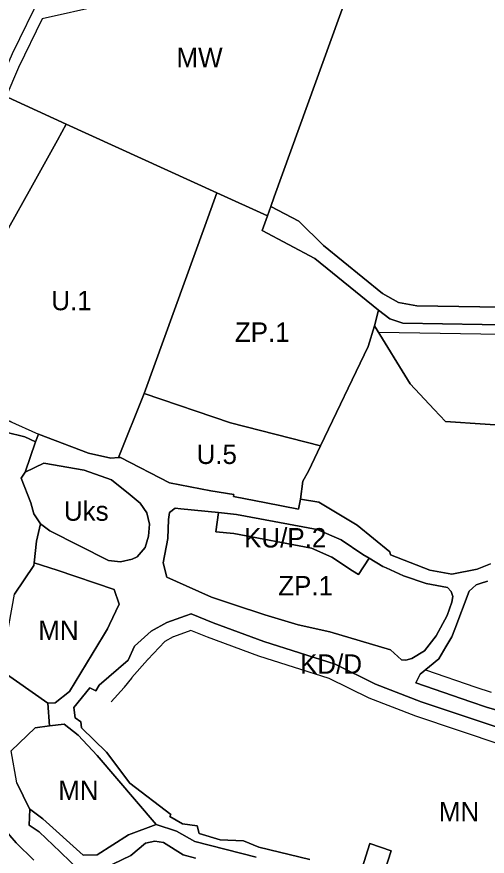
# Model space of a CAD drawing. Extents: x 7438199 to 7440548, y 5549253 to 5551017.
# Drawn here: x 7438917.7 to 7439160, y 5550359.8 to 5550792.4 of the extents above; entities that cross this region are included whole.
import ezdxf

# ---------------------------------------------------------------- set-up
doc = ezdxf.new("R2010")
doc.units = 0
for name, color, linetype in [('linie_rozgraniczajace', 7, 'Continuous'), ('linie_zabudowy_nieprzekraczalne', 7, 'Continuous'), ('oznaczenia_przeznaczen', 7, 'Continuous')]:
    doc.layers.add(name, color=color, linetype=linetype)

msp = doc.modelspace()

# ---------------------------------------------------------------- linework, layer by layer
at = {"layer": 'linie_rozgraniczajace'}
for points in [[(7439177.79, 5550642.53), (7439123.74, 5550643.4), (7439114.3, 5550645.13), (7439106.06, 5550649.82), (7439075.72, 5550674.59), (7439062.98, 5550687.02), (7439048.59, 5550694.66), (7439050.34, 5550699.54), (7439092.49, 5550816.41), (7439102.58, 5550833.38), (7439108.69, 5550843.65), (7439167.88, 5550856.79)], [(7439179.38, 5550581.08), (7439138.49, 5550583.87), (7439132.67, 5550590.05), (7439120.33, 5550603.16), (7439101.88, 5550633.22), (7439104.03, 5550641.16), (7439109.78, 5550636.73), (7439116.56, 5550634.52), (7439177.91, 5550633.53)], [(7439161.71, 5550510.48), (7439154.78, 5550507.8), (7439141.85, 5550505.11), (7439130.53, 5550507.27), (7439110.16, 5550515.09), (7439109.86, 5550516.66), (7439093.02, 5550530.41), (7439073.3, 5550542.24), (7439063.8, 5550543.89), (7439065.05, 5550553.1), (7439067.91, 5550558.25), (7439074.21, 5550571.36), (7439098.71, 5550622.41), (7439101.88, 5550633.22), (7439120.33, 5550603.16), (7439132.67, 5550590.05), (7439138.49, 5550583.87), (7439179.38, 5550581.08)], [(7438912.06, 5550578.32), (7438921.86, 5550575.86), (7438927.29, 5550573.44), (7438921.93, 5550557.8), (7438919.98, 5550554.57), (7438925, 5550541.97), (7438926.54, 5550536.25), (7438929.88, 5550531.11), (7438927.79, 5550522.1), (7438926.58, 5550511), (7438926.49, 5550509.6), (7438916.57, 5550494.9)], [(7438921.93, 5550557.8), (7438927.29, 5550573.44), (7438928.95, 5550577.22), (7438954.64, 5550567.5), (7438966.11, 5550565.02), (7438970.07, 5550565.25), (7438971.03, 5550565.31), (7438996.38, 5550552.24), (7439017.67, 5550548.08), (7439029.5, 5550546.2), (7439029.24, 5550545.14), (7439046.12, 5550541.89), (7439062.82, 5550538.64), (7439063.8, 5550543.89), (7439073.3, 5550542.24), (7439093.02, 5550530.41), (7439109.86, 5550516.66), (7439110.16, 5550515.09), (7439130.53, 5550507.27), (7439141.85, 5550505.11), (7439154.78, 5550507.8), (7439161.71, 5550510.48)], [(7439040.93, 5550359.25), (7439009.39, 5550367.36), (7439000.02, 5550372.78), (7438989.51, 5550376.09), (7438959.12, 5550411.62), (7438949.38, 5550422.2), (7438942.08, 5550427.87), (7438934.63, 5550426.93), (7438933.68, 5550438.7), (7438937.38, 5550438.78), (7438944.88, 5550444.76), (7438962.44, 5550473.61), (7438964.49, 5550476.99), (7438965.51, 5550479.19), (7438970.36, 5550489.69), (7438967.77, 5550497.26), (7438938.54, 5550507.28), (7438926.58, 5550511), (7438927.79, 5550522.1), (7438929.88, 5550531.11), (7438934.7, 5550527.53), (7438964.92, 5550512.24), (7438971.16, 5550511.59), (7438977.1, 5550512.88), (7438979.77, 5550514.16), (7438983.79, 5550518.87), (7438985.55, 5550524.69), (7438986.13, 5550530.93), (7438984.7, 5550536.84), (7438981.17, 5550541.81), (7438976.18, 5550546.03), (7438966.53, 5550553.83), (7438952.32, 5550558.75), (7438931.59, 5550562.33), (7438921.93, 5550557.8)], [(7438926.4, 5550357.75), (7438917.29, 5550366.61), (7438914.15, 5550370.51), (7438911.03, 5550374.37), (7438905.07, 5550382.61), (7438904.82, 5550391.79), (7438904.81, 5550391.93), (7438900.69, 5550408.48), (7438896.57, 5550425.02), (7438896.35, 5550434.12), (7438895.93, 5550434.08), (7438895.8, 5550440.56), (7438895.66, 5550447.04), (7438898.89, 5550478.66), (7438902.26, 5550498.06), (7438904.14, 5550511.19), (7438906.44, 5550525.8), (7438906.48, 5550528.4), (7438906.82, 5550532.42), (7438905.55, 5550538.97), (7438898.26, 5550554.64), (7438894.22, 5550560.43)], [(7439165.04, 5550435.05), (7439159.63, 5550436.68), (7439151.52, 5550439.4), (7439123.16, 5550449.19), (7439125.46, 5550453.6), (7439135.13, 5550461.44), (7439138.77, 5550467.69), (7439141.82, 5550472.91), (7439143.26, 5550476.75), (7439150.65, 5550496.42), (7439152.47, 5550498.02), (7439154.28, 5550499.62), (7439156.39, 5550500.39), (7439160.1, 5550501.6)], [(7439160.1, 5550501.6), (7439156.39, 5550500.39), (7439154.28, 5550499.62), (7439152.47, 5550498.02), (7439150.65, 5550496.42), (7439143.26, 5550476.75), (7439141.82, 5550472.91), (7439138.77, 5550467.69), (7439135.13, 5550461.44), (7439125.46, 5550453.6), (7439123.16, 5550449.19), (7439151.52, 5550439.4), (7439159.63, 5550436.68), (7439165.04, 5550435.05)], [(7439068.64, 5550358.03), (7439042.41, 5550364.47), (7439034.53, 5550367.69), (7439022.39, 5550368.18), (7439011.58, 5550371.45), (7439010.52, 5550375.5), (7439003.12, 5550376.46), (7438996.56, 5550380.24), (7438997.01, 5550381.31), (7438975.91, 5550397.51), (7438963.83, 5550413.48), (7438951.11, 5550426), (7438950.63, 5550428.97), (7438947.82, 5550431.05), (7438947.14, 5550436.52), (7438955.32, 5550446.51), (7438958.4, 5550445), (7438960.11, 5550447.98), (7438975.12, 5550460.85), (7438978.33, 5550468.09), (7438986.91, 5550475.78), (7438994.99, 5550480.18), (7439004.67, 5550483.68), (7439007.52, 5550484.71), (7439018.81, 5550480.12), (7439044.91, 5550470.46), (7439081.63, 5550458.83), (7439102.44, 5550448.53), (7439125.97, 5550439.44), (7439170.32, 5550424.55)], [(7439170.32, 5550424.55), (7439125.97, 5550439.44), (7439102.44, 5550448.53), (7439081.63, 5550458.83), (7439044.91, 5550470.46), (7439018.81, 5550480.12), (7439007.52, 5550484.71), (7439004.67, 5550483.68), (7438994.99, 5550480.18), (7438986.91, 5550475.78), (7438978.33, 5550468.09), (7438975.12, 5550460.85), (7438960.11, 5550447.98), (7438958.4, 5550445), (7438955.32, 5550446.51), (7438947.14, 5550436.52), (7438947.82, 5550431.05), (7438950.63, 5550428.97), (7438951.11, 5550426), (7438963.83, 5550413.48), (7438975.91, 5550397.51), (7438997.01, 5550381.31), (7438996.56, 5550380.24), (7439003.12, 5550376.46), (7439010.52, 5550375.5), (7439011.58, 5550371.45), (7439022.39, 5550368.18), (7439034.53, 5550367.69), (7439042.41, 5550364.47), (7439068.64, 5550358.03)], [(7438909.55, 5550455.66), (7438933.68, 5550438.7), (7438934.63, 5550426.93), (7438927.18, 5550426), (7438914.85, 5550414.19)], [(7438787.79, 5550355.53), (7438796.75, 5550368.59), (7438813.34, 5550396.85), (7438817.34, 5550400.58), (7438821.33, 5550404.09), (7438826.88, 5550406.22), (7438833.47, 5550406.62), (7438840.95, 5550404.64), (7438845.84, 5550402.45), (7438864.2, 5550394.06), (7438882.86, 5550385.45), (7438886.22, 5550391.53), (7438905.07, 5550382.61), (7438911.03, 5550374.37), (7438914.15, 5550370.51), (7438917.29, 5550366.61), (7438926.4, 5550357.75)], [(7438917.65, 5550397.54), (7438924.31, 5550384.19), (7438924.35, 5550384.13), (7438924.1, 5550375.84), (7438929.23, 5550372.42), (7438939.98, 5550362.05), (7438950.72, 5550351.67)], [(7438950.72, 5550351.67), (7438939.98, 5550362.05), (7438929.23, 5550372.42), (7438924.1, 5550375.84), (7438924.35, 5550384.13), (7438924.31, 5550384.19), (7438931.15, 5550379.14), (7438951.8, 5550360.38), (7438959.14, 5550360.57), (7438975.32, 5550370.81), (7438989.51, 5550376.09), (7439000.02, 5550372.78), (7439009.39, 5550367.36), (7439040.93, 5550359.25)], [(7438958.22, 5550351.34), (7438976.46, 5550360.11), (7438983.99, 5550366.45), (7438988.75, 5550367.61), (7438993.22, 5550366.92), (7439003.36, 5550360.49), (7439009.74, 5550358.8)], [(7439009.74, 5550358.8), (7439003.36, 5550360.49), (7438993.22, 5550366.92), (7438988.75, 5550367.61), (7438983.99, 5550366.45), (7438976.46, 5550360.11), (7438958.22, 5550351.34)], [(7439106.84, 5550351.42), (7439110.46, 5550362.5), (7439105.01, 5550364.44), (7439099.56, 5550366.37), (7439095.55, 5550353.74)], [(7439095.55, 5550353.74), (7439099.56, 5550366.37), (7439105.01, 5550364.44), (7439110.46, 5550362.5), (7439106.84, 5550351.42)]]:
    msp.add_lwpolyline(points, dxfattribs=at)
for points in [[(7438906.66, 5550753.65), (7438915.42, 5550773.41), (7438930.38, 5550804.29), (7438991.1, 5550818.07), (7439026, 5550825.99), (7439042.73, 5550830.95), (7439048.59, 5550832.62), (7439095.81, 5550842.97), (7439096.81, 5550837.3), (7439096, 5550833.11), (7439095.84, 5550832.32), (7439096.59, 5550828.7), (7439092.49, 5550816.41), (7439050.34, 5550699.54), (7439048.59, 5550694.66), (7439046.85, 5550689.8), (7439020.82, 5550701.66), (7438943.17, 5550737.02)], [(7438864.25, 5550654.48), (7438868.71, 5550671.05), (7438876.14, 5550698.63), (7438889.91, 5550723.46), (7438903.68, 5550748.28), (7438906.66, 5550753.65), (7438943.17, 5550737.02), (7438938.66, 5550728.88), (7438924.89, 5550704.05), (7438913.49, 5550683.5), (7438907.33, 5550660.65), (7438902.8, 5550643.82)], [(7438856.2, 5550623.73), (7438861.28, 5550643.47), (7438864.25, 5550654.48), (7438902.8, 5550643.82), (7438907.33, 5550660.65), (7438913.49, 5550683.5), (7438924.89, 5550704.05), (7438938.66, 5550728.88), (7438943.17, 5550737.02), (7439020.82, 5550701.66), (7439014.6, 5550684.53), (7438983.31, 5550598.22), (7438970.07, 5550565.25), (7438966.11, 5550565.02), (7438954.64, 5550567.5), (7438928.95, 5550577.22), (7438927.29, 5550573.44), (7438921.86, 5550575.86), (7438912.06, 5550578.32), (7438889.4, 5550590.35), (7438870.1, 5550605.3)], [(7438983.31, 5550598.22), (7439014.6, 5550684.53), (7439020.82, 5550701.66), (7439046.85, 5550689.8), (7439044.17, 5550682.29), (7439071.27, 5550667.9), (7439104.03, 5550641.16), (7439101.88, 5550633.22), (7439098.71, 5550622.41), (7439074.21, 5550571.36), (7439027.76, 5550583.08)], [(7439044.17, 5550682.29), (7439046.85, 5550689.8), (7439048.59, 5550694.66), (7439062.98, 5550687.02), (7439075.72, 5550674.59), (7439106.06, 5550649.82), (7439114.3, 5550645.13), (7439123.74, 5550643.4), (7439177.79, 5550642.53), (7439322.46, 5550644.44), (7439329.12, 5550654), (7439340.07, 5550623.13), (7439312.46, 5550633.66), (7439302.38, 5550636.01), (7439253.6, 5550634.86), (7439239.07, 5550634.34), (7439177.91, 5550633.53), (7439116.56, 5550634.52), (7439109.78, 5550636.73), (7439104.03, 5550641.16), (7439071.27, 5550667.9)], [(7438970.07, 5550565.25), (7438983.31, 5550598.22), (7439027.76, 5550583.08), (7439074.21, 5550571.36), (7439067.91, 5550558.25), (7439065.05, 5550553.1), (7439063.8, 5550543.89), (7439062.82, 5550538.64), (7439046.12, 5550541.89), (7439029.24, 5550545.14), (7439029.5, 5550546.2), (7439017.67, 5550548.08), (7438996.38, 5550552.24), (7438971.03, 5550565.31)], [(7438919.98, 5550554.57), (7438921.93, 5550557.8), (7438931.59, 5550562.33), (7438952.32, 5550558.75), (7438966.53, 5550553.83), (7438976.18, 5550546.03), (7438981.17, 5550541.81), (7438984.7, 5550536.84), (7438986.13, 5550530.93), (7438985.55, 5550524.69), (7438983.79, 5550518.87), (7438979.77, 5550514.16), (7438977.1, 5550512.88), (7438971.16, 5550511.59), (7438964.92, 5550512.24), (7438934.7, 5550527.53), (7438929.88, 5550531.11), (7438926.54, 5550536.25), (7438925, 5550541.97)], [(7438993.01, 5550511), (7438995.51, 5550523.51), (7438995.9, 5550533.35), (7438996.44, 5550537.02), (7438999.28, 5550539.11), (7439002.15, 5550538.82), (7439021.65, 5550536.86), (7439020.29, 5550526.95), (7439029.47, 5550526.03), (7439069.48, 5550518.61), (7439079.93, 5550513.99), (7439090.61, 5550506.88), (7439093.79, 5550504.94), (7439099.26, 5550513.32), (7439106.17, 5550509.1), (7439107.89, 5550508.34), (7439116.96, 5550504.33), (7439128.52, 5550500.43), (7439139.47, 5550498.21), (7439141.39, 5550496.22), (7439142.34, 5550493.63), (7439141.78, 5550490.65), (7439139.32, 5550483.93), (7439133.79, 5550473.43), (7439127.71, 5550465.71), (7439121.16, 5550461.66), (7439118, 5550460.85), (7439115.78, 5550460.94), (7439110.11, 5550466.11), (7439078.96, 5550475.41), (7439062.7, 5550479.1), (7439045.53, 5550484.16), (7439029.25, 5550489.56), (7439018.04, 5550493.29), (7439004.93, 5550499.13), (7438994.96, 5550503.56)], [(7438993.01, 5550511), (7438994.96, 5550503.56), (7439004.93, 5550499.13), (7439018.04, 5550493.29), (7439029.25, 5550489.56), (7439045.53, 5550484.16), (7439062.7, 5550479.1), (7439078.96, 5550475.41), (7439110.11, 5550466.11), (7439115.78, 5550460.94), (7439118, 5550460.85), (7439121.16, 5550461.66), (7439127.71, 5550465.71), (7439133.79, 5550473.43), (7439139.32, 5550483.93), (7439141.78, 5550490.65), (7439142.34, 5550493.63), (7439141.39, 5550496.22), (7439139.47, 5550498.21), (7439128.52, 5550500.43), (7439116.96, 5550504.33), (7439107.89, 5550508.34), (7439106.17, 5550509.1), (7439099.26, 5550513.32), (7439095.99, 5550515.31), (7439084.76, 5550522.79), (7439072.45, 5550528.22), (7439030.89, 5550535.93), (7439021.65, 5550536.86), (7439002.15, 5550538.82), (7438999.28, 5550539.11), (7438996.44, 5550537.02), (7438995.9, 5550533.35), (7438995.51, 5550523.51)], [(7439020.29, 5550526.95), (7439021.65, 5550536.86), (7439030.89, 5550535.93), (7439072.45, 5550528.22), (7439084.76, 5550522.79), (7439095.99, 5550515.31), (7439099.26, 5550513.32), (7439093.79, 5550504.94), (7439090.61, 5550506.88), (7439079.93, 5550513.99), (7439069.48, 5550518.61), (7439029.47, 5550526.03)], [(7438909.55, 5550455.66), (7438916.57, 5550494.9), (7438926.49, 5550509.6), (7438926.58, 5550511), (7438938.54, 5550507.28), (7438967.77, 5550497.26), (7438970.36, 5550489.69), (7438965.51, 5550479.19), (7438964.49, 5550476.99), (7438962.44, 5550473.61), (7438944.88, 5550444.76), (7438937.38, 5550438.78), (7438933.68, 5550438.7)], [(7438914.85, 5550414.19), (7438927.18, 5550426), (7438934.63, 5550426.93), (7438942.08, 5550427.87), (7438949.38, 5550422.2), (7438959.12, 5550411.62), (7438989.51, 5550376.09), (7438975.32, 5550370.81), (7438959.14, 5550360.57), (7438951.8, 5550360.38), (7438931.15, 5550379.14), (7438924.31, 5550384.19), (7438917.65, 5550397.54)]]:
    msp.add_lwpolyline(points, close=True, dxfattribs=at)
at = {"layer": 'linie_zabudowy_nieprzekraczalne'}
for points in [[(7439095.37, 5550829.88), (7439051.74, 5550820.31), (7439029.48, 5550813.78), (7438992.26, 5550805.31), (7438930.79, 5550791.35), (7438918.61, 5550766.23), (7438912.04, 5550750.97), (7438908.93, 5550745.37), (7438881.74, 5550696.36), (7438867.22, 5550642.45), (7438866, 5550626.32), (7438874.82, 5550609.23), (7438892.67, 5550595.4), (7438914.88, 5550583.61), (7438913.52, 5550584.14), (7438928.95, 5550577.22)], [(7439177.83, 5550628.53), (7439104.13, 5550629.72)], [(7439167.76, 5550416.97), (7439123.26, 5550431.91), (7439099.21, 5550441.2), (7439078.63, 5550451.39), (7439042.32, 5550462.89), (7439015.92, 5550472.66), (7439007.35, 5550476.14), (7438998.34, 5550472.88), (7438998.28, 5550472.86), (7438998.26, 5550472.84), (7438993.98, 5550470.53), (7438993.97, 5550470.52), (7438993.94, 5550470.49), (7438985.13, 5550461.23), (7438985.04, 5550461.14), (7438984.96, 5550461.04), (7438977.01, 5550451.86), (7438976.87, 5550451.7), (7438976.81, 5550451.63), (7438973.05, 5550446.88), (7438973, 5550446.81), (7438972.92, 5550446.72), (7438966.32, 5550439.35)], [(7439128.28, 5550455.89), (7439154.1, 5550446.97), (7439162.06, 5550444.3)]]:
    msp.add_lwpolyline(points, dxfattribs=at)

# ---------------------------------------------------------------- texts
at = {"layer": 'oznaczenia_przeznaczen'}
for s, p in [('MW', (7438999.95, 5550766.42)), ('U.1', (7438935.45, 5550641.17)), ('ZP.1', (7439030, 5550624.89)), ('U.5', (7439010.28, 5550561.94)), ('Uks', (7438941.96, 5550532.68)), ('KU/P.2', (7439034.77, 5550518.9)), ('ZP.1', (7439052.34, 5550494.21)), ('MN', (7438928.75, 5550471.22)), ('KD/D', (7439063.6, 5550453.83)), ('MN', (7438939.04, 5550388.71)), ('MN', (7439135.1, 5550377.73))]:
    msp.add_text(s, height=10, dxfattribs=at).set_placement(p)

doc.saveas('drawing.dxf')
